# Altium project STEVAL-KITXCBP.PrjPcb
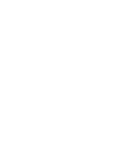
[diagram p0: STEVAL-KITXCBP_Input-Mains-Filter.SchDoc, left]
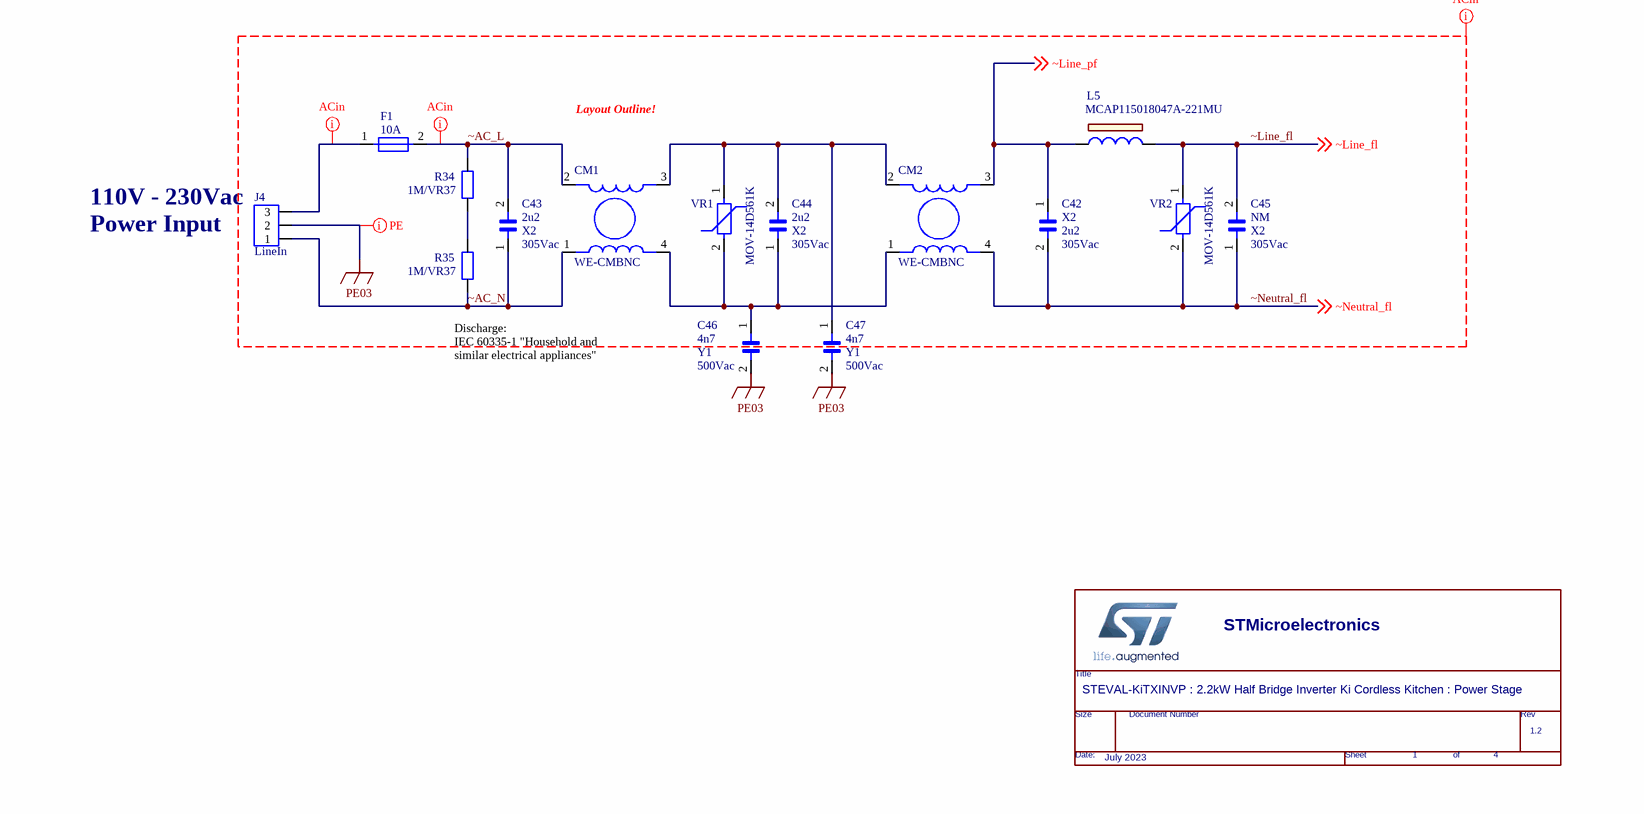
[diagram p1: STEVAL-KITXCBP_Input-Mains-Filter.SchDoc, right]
3 sheets, 268 parts. Net scope: global (net labels, ports and power ports of the same name join across sheets).
Board file: STEVAL-KITXCBP.PcbDoc
Sheets:
  STEVAL-KITXCBP_Input-Mains-Filter.SchDoc
  STEVAL-KITXCBP_Power-Stage.SchDoc
  STEVAL-KITXCBP_Voltage-Regulator.SchDoc

## Sheet STEVAL-KITXCBP_Input-Mains-Filter.SchDoc
size A4; SheetNumber: 1; SheetTotal: 4; PageSetup: Record=PageOptions¦CenterHorizontal=True¦CenterVertical=True¦PrintScale=0.73¦XCorrection=1.00¦YCorrection=1.00¦PrintKind=0¦BorderSize=5000000¦LeftOffset=0¦BottomOffset=0¦Orientation=2¦PaperLength=1000¦PaperWidth=1000¦Scale=100¦PaperSource=15¦PrintQuality=-3¦MediaType=1¦DitherType=10¦PrintScaleMode=1¦PaperKind=A3¦PaperIndex=8

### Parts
(Parts that share a designator on the sheet are numbered #1, #2 ... from top to bottom, then left to right.)
*?#1  Page Create Date: July 2023  RevCode: 1.2  Title: STEVAL-KiTXINVP : 2.2kW Half Bridge Inverter Ki Cordless Kitchen : Power Stage  Page Number: 1  Page Count: 4  (hidden comment: ST_Standard_TitleBlock)  (graphical)
C42  2u2  Dielectric: X2  Voltage: 305Vac  [BLK 13.5 X 32 X P27.5]
C43  2u2  Dielectric: X2  Voltage: 305Vac  [BLK 13.5 X 32 X P27.5]
C44  2u2  Dielectric: X2  Voltage: 305Vac  [BLK 13.5 X 32 X P27.5]
C45  NM  Dielectric: X2  Voltage: 305Vac  [BLK 13.5 X 32 X P27.5]
C46  4n7  Dielectric: Y1  Voltage: 500Vac  [BLK 6X12.5XP10 H12]
C47  4n7  Dielectric: Y1  Voltage: 500Vac  [BLK 6X12.5XP10 H12]
CM1  WE-CMBNC  [WE-CMBNC-MULTI-FOOTPRINT]
CM2  WE-CMBNC  [WE-CMBNC-MULTI-FOOTPRINT]
F1  10A  [FUSEHOLDER]
J4  LineIn  [PX0580/PC]
L5  MCAP115018047A-221MU  [MCAP115018047A]
R34  1M/VR37  [AXIAL0.5]
R35  1M/VR37  [AXIAL0.5]
VR1  MOV-14D561K  [Varistor 14mm]
VR2  MOV-14D561K  [Varistor 14mm]

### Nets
PE03: C46.2 C47.2 J4.2
~AC_L: C43.2 CM1.2 F1.2 R34.2
~AC_N: C43.1 CM1.1 J4.1 R35.1
~Line_fl: C45.2 L5.2 VR2.1 ; off-sheet ~Line_fl  [project net ~Line]
~Line_pf: C42.1 CM2.3 L5.1 ; off-sheet ~Line_pf
~Neutral_fl: C42.2 C45.1 CM2.4 VR2.2 ; off-sheet ~Neutral_fl  [project net ~Neutral]
NetC44_1: C44.1 C46.1 CM1.4 CM2.1 VR1.2
NetC44_2: C44.2 C47.1 CM1.3 CM2.2 VR1.1
NetF1_1: F1.1 J4.3
NetR34_1: R34.1 R35.2

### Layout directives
net class ACin: NetF1_1, PE03, ~AC_L, ~AC_N, ~Line_fl, ~Line_pf, ~Neutral_fl
net class PE: PE03

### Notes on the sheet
- Layout Outline!
- (near J4) 110V - 230Vac
- Power Input
- (near R35) Discharge:
  IEC 60335-1 "Household and similar electrical appliances"

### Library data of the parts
C42-C44 = CAP NP: Capacitor  Non-Polarised; Manufacturer 1: EPCOS; MPN 1: B32924C3225M000; SMT/THT: THT
C45 = CAP NP: Capacitor  Non-Polarised; Manufacturer 1: EPCOS; MPN 1: B32924C3225M000; SMT/THT: THT; Value: 2u2
C46 C47 = CAP NP: Capacitor  Non-Polarised; Manufacturer 1: VISHAY; MPN 1: VY1472M51Y5VQ63V0; SMT/THT: THT; Value: 4n7/Y1
CM1 CM2 = WE-CMBNC: Common Mode Power Line Choke; Manufacturer 1: WURTH ELEKTRONIK; MPN 1: 7448051012; Value: 12mH/10A
F1 = F: FuseHolder 5x20mm
J4 = HEADER3: Power Entry Connector, Plug, 250 VAC, 10 A; Manufacturer 1: Bulgin; MPN 1: PX0580PC; SMT/THT: THT; Value: PX0580PC
L5 = INDUCTOR FERRITE: Inductor 200mH; SMT/THT: THT
R34 = RESISTOR: Resitor Axial; Manufacturer 1: VISHAY; Rated Power: 500mW; SMT/THT: THT; Voltage: 3500V
R35 = RESISTOR: Resitor Axial; Manufacturer 1: VISHAY; MPN 1: VR37000001004JA100; Rated Power: 500mW; SMT/THT: THT; Voltage: 3500V
VR1 VR2 = RVA: Varistor 14mm disc, 350 Vrms, Vdc=560V@1mA,  Pitch=7.5mm; Rated Power: 125J; SMT/THT: THT; Voltage: 350V

## Sheet STEVAL-KITXCBP_Power-Stage.SchDoc
size A2; SheetNumber: 2; SheetTotal: 4; PageSetup: Record=PageOptions¦CenterHorizontal=True¦CenterVertical=True¦PrintScale=0.73¦XCorrection=1.00¦YCorrection=1.00¦PrintKind=0¦BorderSize=5000000¦LeftOffset=0¦BottomOffset=0¦Orientation=2¦PaperLength=1000¦PaperWidth=1000¦Scale=100¦PaperSource=15¦PrintQuality=-3¦MediaType=1¦DitherType=10¦PrintScaleMode=1¦PaperKind=A3¦PaperIndex=8
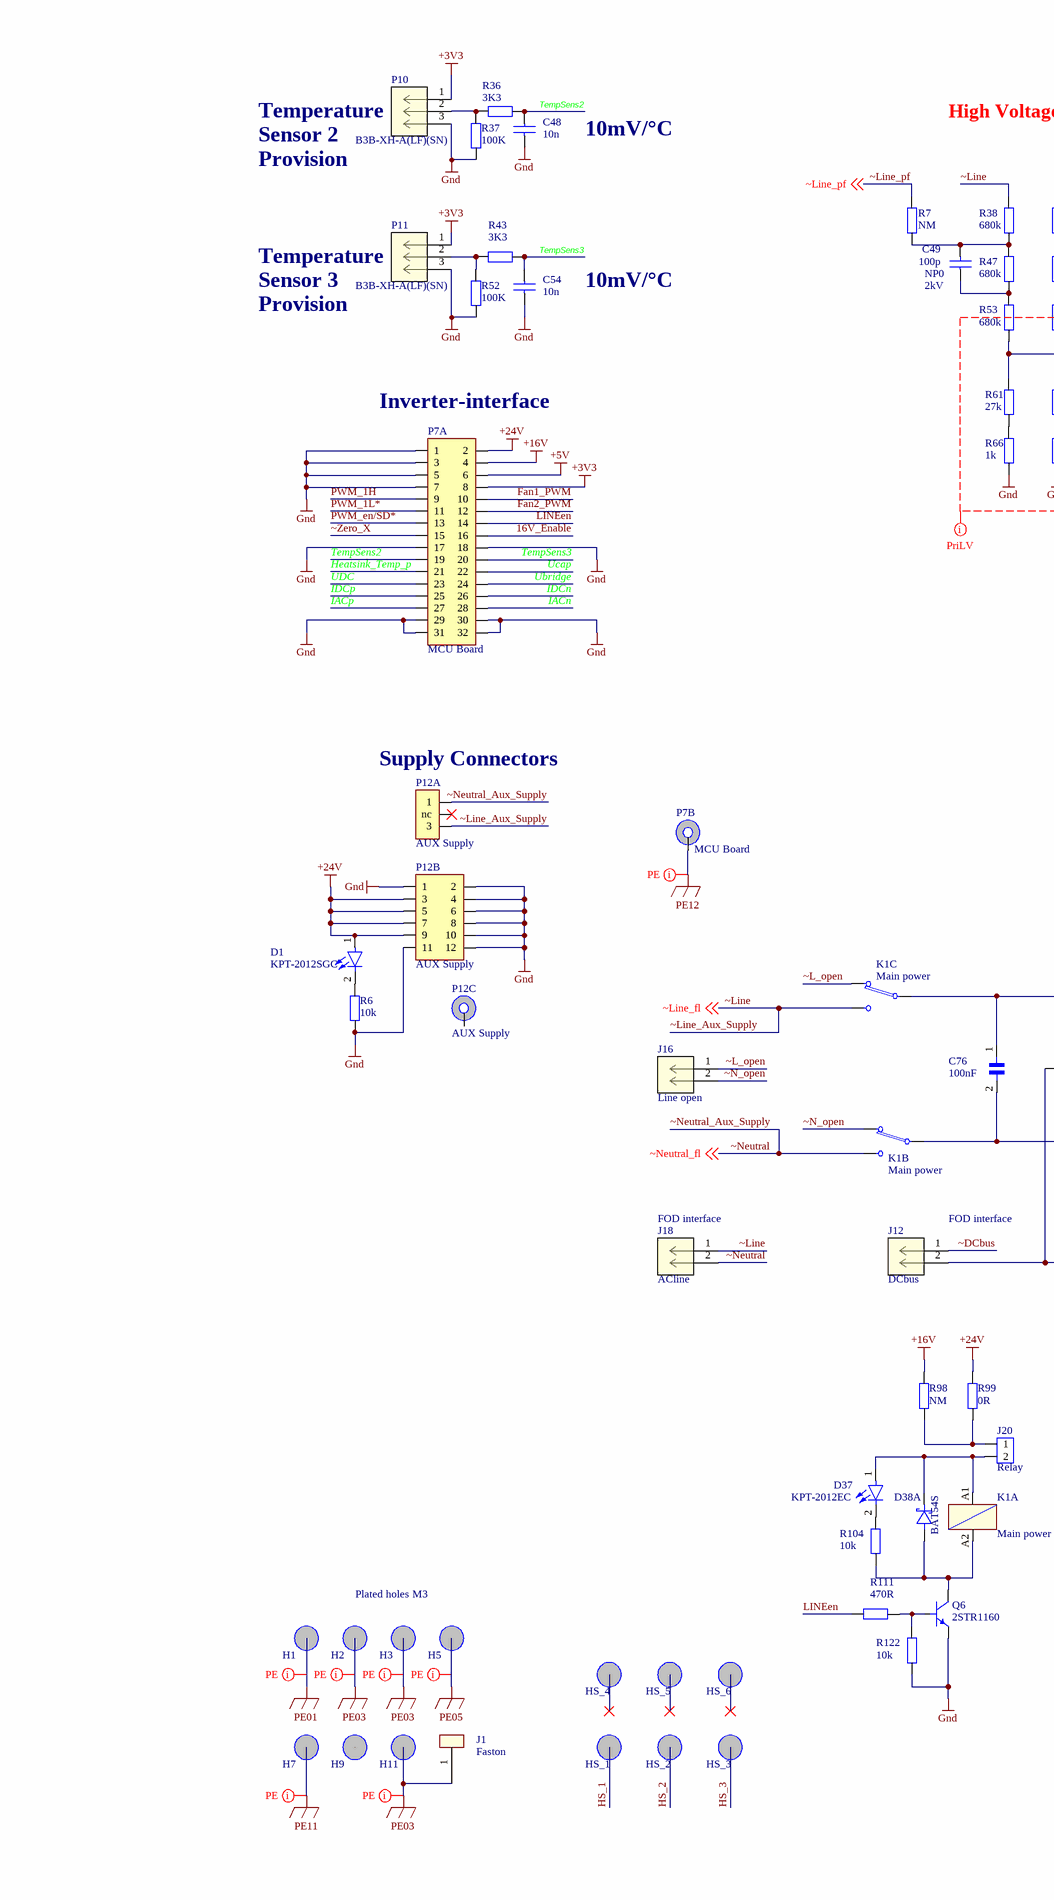
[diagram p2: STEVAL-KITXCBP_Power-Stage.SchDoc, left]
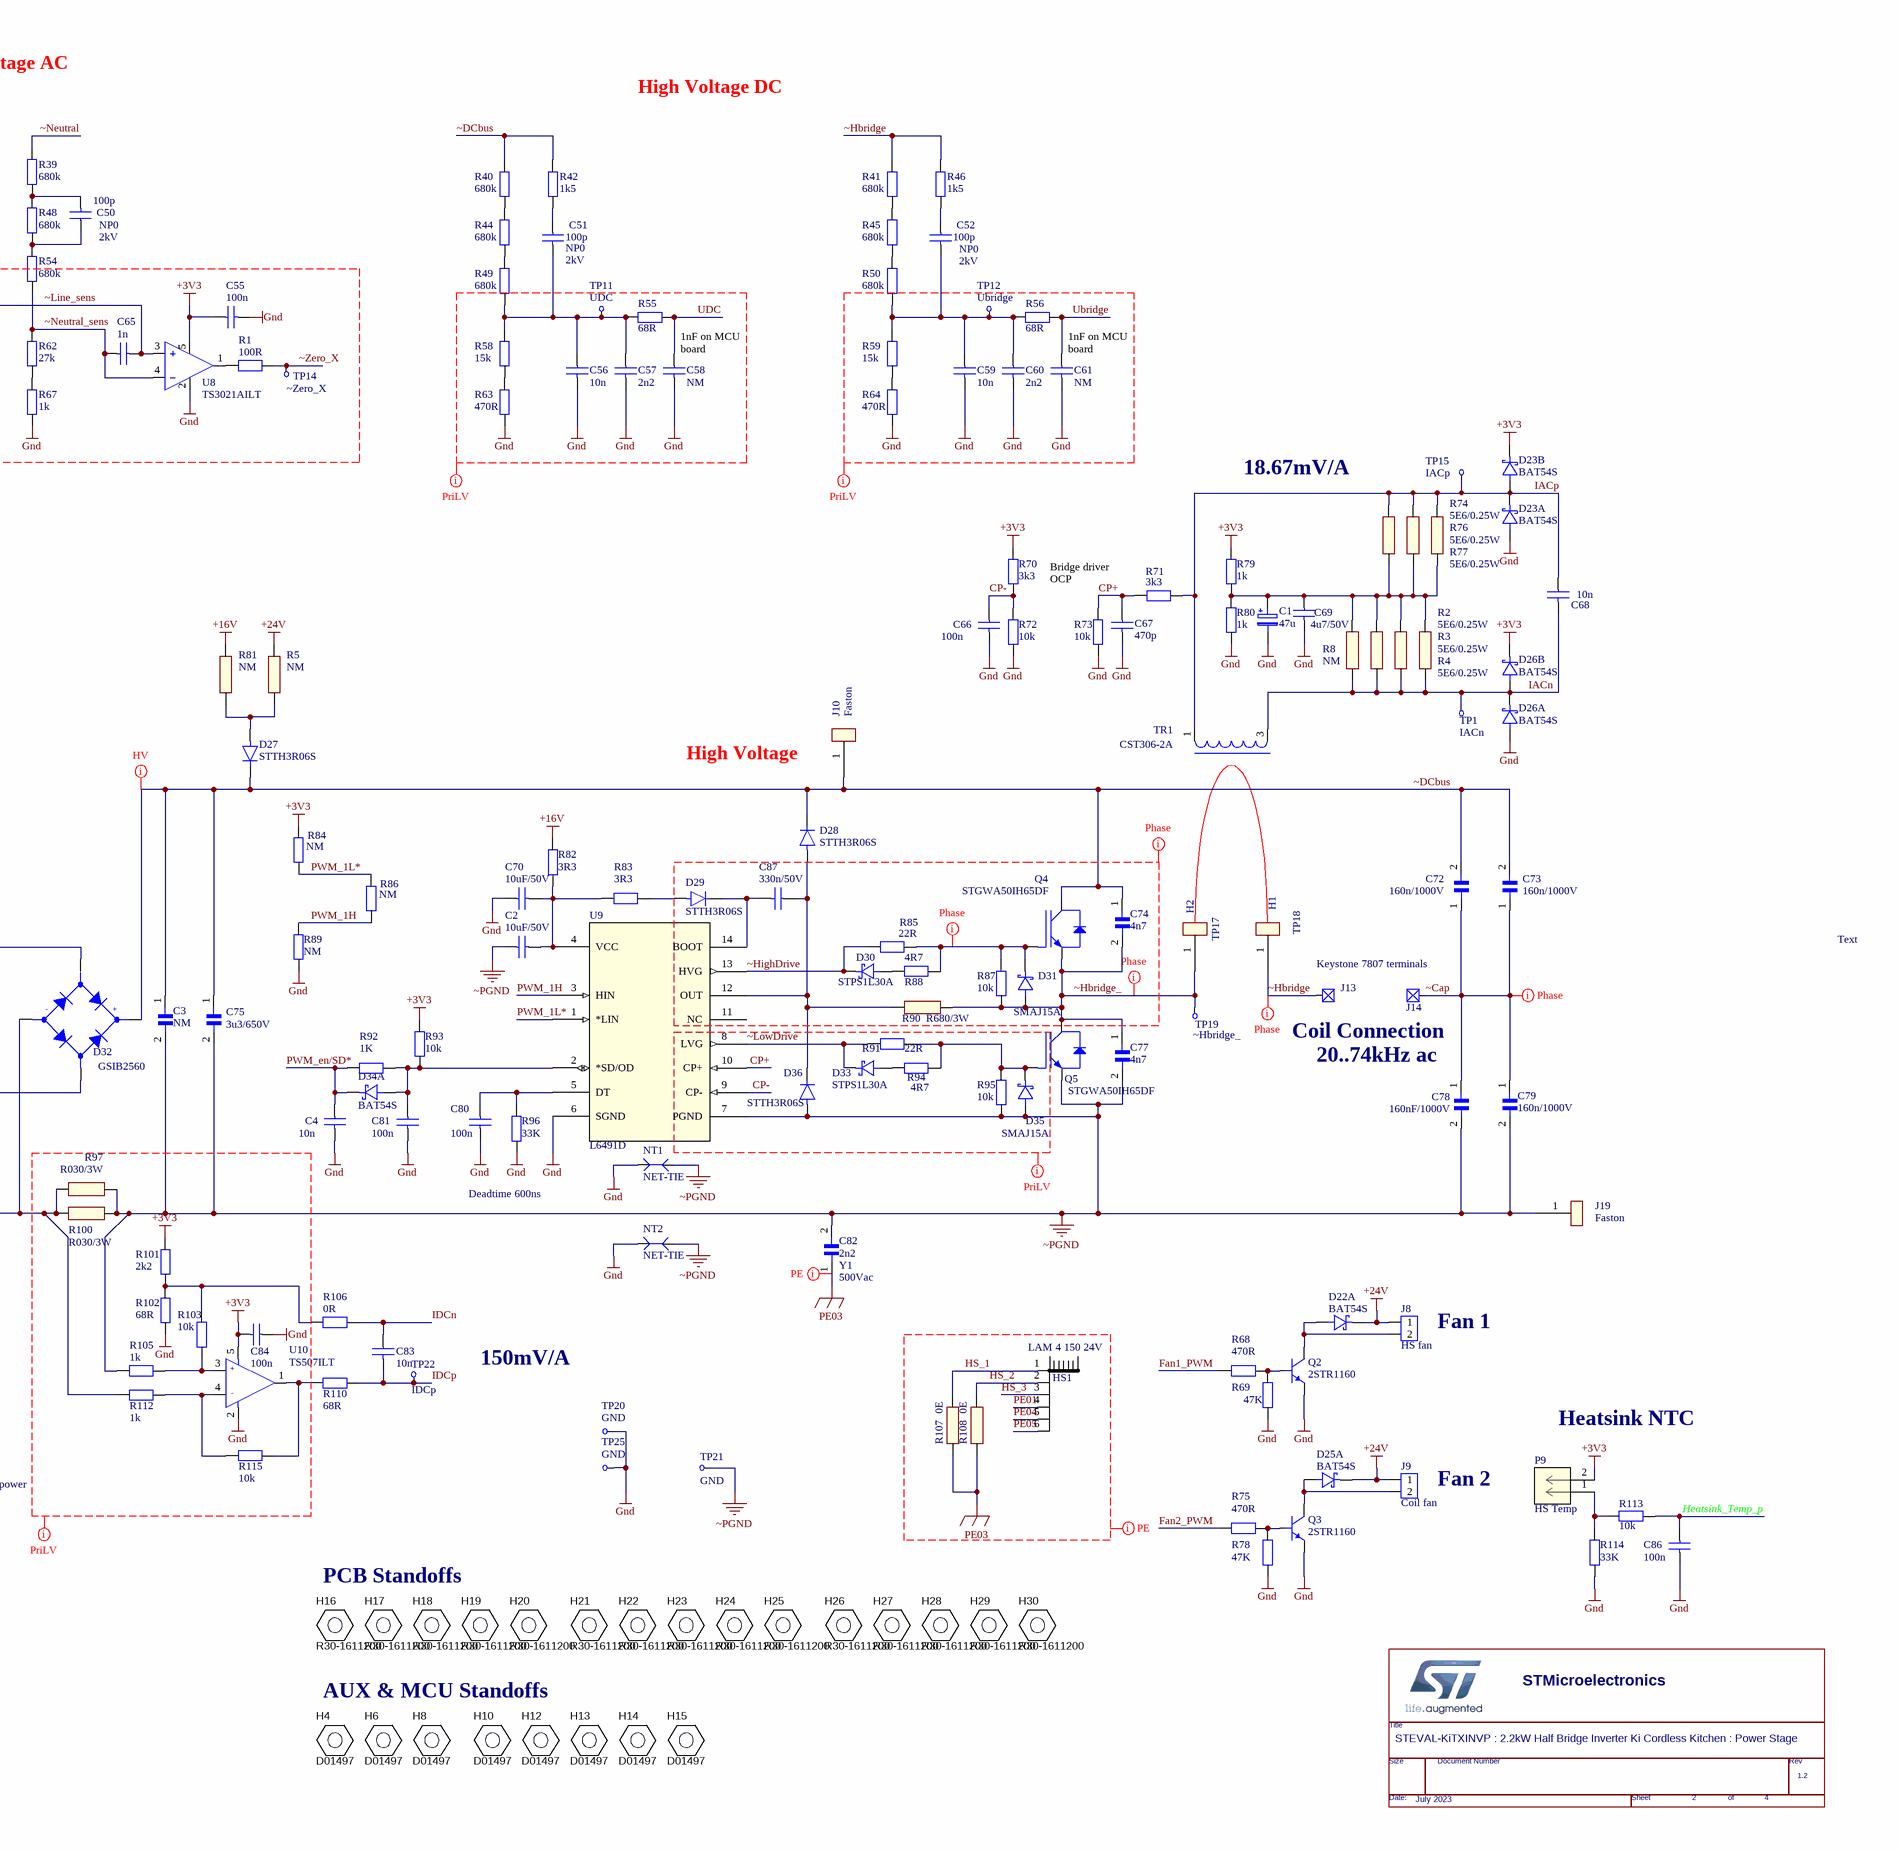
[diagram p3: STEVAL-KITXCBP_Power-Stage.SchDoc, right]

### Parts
(Parts that share a designator on the sheet are numbered #1, #2 ... from top to bottom, then left to right.)
*?#2  Page Create Date: July 2023  RevCode: 1.2  Title: STEVAL-KiTXINVP : 2.2kW Half Bridge Inverter Ki Cordless Kitchen : Power Stage  Page Number: 2  Page Count: 4  (hidden comment: ST_Standard_TitleBlock)  (graphical)
C1  47u  [ELCAP SMD D5H5.8P1.5]
C2  10uF/50V  [CC1210]
C3  NM  [CAPRR1500W80L1800T800H1500A]
C4  10n  [CC0805]
C48  10n  [SMD 0805 CAP]
C49  100p  Dielectric: NP0  Voltage: 2kV  [SMD 1206 CAP]
C50  100p  Dielectric: NP0  Voltage: 2kV  [SMD 1206 CAP]
C51  100p  Dielectric: NP0  Voltage: 2kV  [SMD 1206 CAP]
C52  100p  Dielectric: NP0  Voltage: 2kV  [SMD 1206 CAP]
C54  10n  [SMD 0805 CAP]
C55  100n  [SMD 0805 CAP]
C56  10n  [SMD 0805 CAP]
C57  2n2  [SMD 0805 CAP]
C58  NM  [SMD 0805 CAP]
C59  10n  [SMD 0805 CAP]
C60  2n2  [SMD 0805 CAP]
C61  NM  [SMD 0805 CAP]
C65  1n  [SMD 0805 CAP]
C66  100n  [SMD 0805 CAP]
C67  470p  [SMD 0805 CAP]
C68  10n  [SMD 0805 CAP]
C69  4u7/50V  [CAP SMD 1210small H2.4]
C70  10uF/50V  [CAP SMD 1210small H2.4]
C72  160n/1000V  [Capacitor  Non-Polarised]
C73  160n/1000V  [Capacitor  Non-Polarised]
C74  4n7  [CAPRR1500W80L1800T800H1500A]
C75  3u3/650V  [BLK 22 X 32 X P27.5 H37]
C76  100nF  [BLK 5X18XP15]
C77  4n7  [CAPRR1500W80L1800T800H1500A]
C78  160nF/1000V  [Capacitor  Non-Polarised]
C79  160n/1000V  [Capacitor  Non-Polarised]
C80  100n  [SMD 0805 CAP]
C81  100n  [SMD 0805 CAP]
C82  2n2  Dielectric: Y1  Voltage: 500Vac  [CAPRB1000W60L950T550H1350]
C83  10n  [SMD 0805 CAP]
C84  100n  [SMD 0805 CAP]
C86  100n  [SMD 0805 CAP]
C87  330n/50V  [CAP SMD 1210small H2.4]
D1  KPT-2012SGC  [LED_KPT-2012EC]
D22  BAT54S  [SOT23_3]  (part A of 2)
D23  BAT54S  [SOT23_3]  (parts A,B of 2)
D25  BAT54S  [SOT23_3]  (part A of 2)
D26  BAT54S  [SOT23_3]  (parts A,B of 2)
D27  STTH3R06S  [DO214AB-SMC]
D28  STTH3R06S  [DO214AB-SMC]
D29  STTH3R06S  [DO214AB-SMC]
D30  STPS1L30A  [DO214AC-SMA]
D31  SMAJ15A  [DO214AC-SMA]
D32  GSIB2560  [SIP_GSIB2560-E3/45]
D33  STPS1L30A  [DO214AC-SMA]
D34  BAT54S  [SOT23_3]  (part A of 2)
D35  SMAJ15A  [DO214AC-SMA]
D36  STTH3R06S  [DO214AB-SMC]
D37  KPT-2012EC  [LED_KPT-2012EC]
D38  BAT54S  [SOT23_3]  (part A of 2)
H1  Hole  [p-hole-m3]  (value not drawn)  (no BOM)
H2  Hole  [p-hole-m3]  (value not drawn)  (no BOM)
H3  Hole  [p-hole-m3]  (value not drawn)  (no BOM)
H4  D01497  [Keystone_1902C]
H5  Hole  [p-hole-m3]  (value not drawn)  (no BOM)
H6  D01497  [Keystone_1902C]
H7  Hole  [p-hole-m3]  (value not drawn)  (no BOM)
H8  D01497  [Keystone_1902C]
H9  Hole  [p-hole-m3]  (value not drawn)  (no BOM)
H10  D01497  [Keystone_1902C]
H11  Hole  [p-hole-m3]  (value not drawn)  (no BOM)
H12  D01497  [Keystone_1902C]
H13  D01497  [Keystone_1902C]
H14  D01497  [Keystone_1902C]
H15  D01497  [Keystone_1902C]
H16  R30-1611200  [Keystone_1902C]
H17  R30-1611200  [Keystone_1902C]
H18  R30-1611200  [Keystone_1902C]
H19  R30-1611200  [Keystone_1902C]
H20  R30-1611200  [Keystone_1902C]
H21  R30-1611200  [Keystone_1902C]
H22  R30-1611200  [Keystone_1902C]
H23  R30-1611200  [Keystone_1902C]
H24  R30-1611200  [Keystone_1902C]
H25  R30-1611200  [Keystone_1902C]
H26  R30-1611200  [Keystone_1902C]
H27  R30-1611200  [Keystone_1902C]
H28  R30-1611200  [Keystone_1902C]
H29  R30-1611200  [Keystone_1902C]
H30  R30-1611200  [Keystone_1902C]
HS1  LAM 4 150 24V  [Heatsink + Fan 150 x 40 x 40mm + Holes]
HS_1  Hole  [p-hole-m3]  (value not drawn)  (no BOM)
HS_2  Hole  [p-hole-m3]  (value not drawn)  (no BOM)
HS_3  Hole  [p-hole-m3]  (value not drawn)  (no BOM)
HS_4  Hole  [p-hole-m3]  (value not drawn)  (no BOM)
HS_5  Hole  [p-hole-m3]  (value not drawn)  (no BOM)
HS_6  Hole  [p-hole-m3]  (value not drawn)  (no BOM)
J1  Faston  [TAB]
J8  HS fan  [CONNECTOR P2.5 MALE]
J9  Coil fan  [CONNECTOR P2.5 MALE]
J10  Faston  [TAB]
J12  DCbus  [Connector P5.08]
J13  7807  [Keystone 7807]  (value not drawn)
J14  7807  [Keystone 7807]  (value not drawn)
J16  Line open  [Connector P5.08]
J18  ACline  [Connector P5.08]
J19  Faston  [TAB]
J20  Relay  [CONNECTOR P2.5 MALE]
K1  Main power  [Finder 44.62]  (parts A,B,C of 3)
NT1  NET-TIE  [Net-Tie-0.3mm]  (net tie, no BOM)
NT2  NET-TIE  [Net-Tie_0805_HV_NoOverlay]  (net tie, no BOM)
P7  MCU Board  [ST MCU BOARD]  (parts A,B of 2)
P9  HS Temp  [CONNECTOR P2.5 MALE]
P10  B3B-XH-A(LF)(SN)  [CONNECTOR P2.5 MALE 3WAY]
P11  B3B-XH-A(LF)(SN)  [CONNECTOR P2.5 MALE 3WAY]
P12  AUX Supply  [ST AUX SUPPLY]  (parts A,B,C of 3)
Q2  2STR1160  [SOT23_3]
Q3  2STR1160  [SOT23_3]
Q4  STGWA50IH65DF  [TO247]
Q5  STGWA50IH65DF  [TO247]
Q6  2STR1160  [SOT23_3]
R1  100R  [SMD 0805]
R2  5E6/0.25W  [VSMP_1206]  (no BOM)
R3  5E6/0.25W  [VSMP_1206]
R4  5E6/0.25W  [VSMP_1206]
R5  NM  [VSMP_2512]  (no BOM)
R6  10k  [RC0805]
R7  NM  [RC1206]
R8  NM  [VSMP_1206]
R36  3K3  [SMD 0805]
R37  100K  [SMD 0805]
R38  680k  [SMD 1206]
R39  680k  [SMD 1206]
R40  680k  [SMD 1206]
R41  680k  [SMD 1206]
R42  1k5  [SMD 1206]
R43  3K3  [SMD 0805]
R44  680k  [SMD 1206]
R45  680k  [SMD 1206]
R46  1k5  [SMD 1206]
R47  680k  [SMD 1206]
R48  680k  [SMD 1206]
R49  680k  [SMD 1206]
R50  680k  [SMD 1206]
R52  100K  [SMD 0805]
R53  680k  [SMD 1206]
R54  680k  [SMD 1206]
R55  68R  [SMD 0805]
R56  68R  [SMD 0805]
R58  15k  [SMD 0805]
R59  15k  [SMD 0805]
R61  27k  [SMD 0805]
R62  27k  [SMD 0805]
R63  470R  [SMD 0805]
R64  470R  [SMD 0805]
R66  1k  [SMD 0805]
R67  1k  [SMD 0805]
R68  470R  [SMD 0805]
R69  47K  [SMD 0805]
R70  3k3  [SMD 0805]
R71  3k3  [SMD 0805]
R72  10k  [SMD 0805]
R73  10k  [SMD 0805]
R74  5E6/0.25W  [VSMP_1206]  (no BOM)
R75  470R  [SMD 0805]
R76  5E6/0.25W  [VSMP_1206]
R77  5E6/0.25W  [VSMP_1206]
R78  47K  [SMD 0805]
R79  1k  [SMD 0805]
R80  1k  [SMD 0805]
R81  NM  [VSMP_2512]  (no BOM)
R82  3R3  [RES SMD 1206]
R83  3R3  [RES SMD 1206]
R84  NM  [SMD 0805]
R85  22R  [SMD 0805]
R86  NM  [SMD 0805]
R87  10k  [SMD 0805]
R88  4R7  [SMD 0805]
R89  NM  [SMD 0805]
R90  R680/3W  [2512welwyn]
R91  22R  [SMD 0805]
R92  1K  [SMD 0805]
R93  10k  [SMD 0805]
R94  4R7  [SMD 0805]
R95  10k  [SMD 0805]
R96  33K  [SMD 0805]
R97  R030/3W  [2512welwyn]
R98  NM  [SMD 0805]  (no BOM)
R99  0R  [SMD 0805]
R100  R030/3W  [2512welwyn]
R101  2k2  [SMD 0805]
R102  68R  [SMD 0805]
R103  10k  [SMD 0805]
R104  10k  [SMD 0805]
R105  1k  [SMD 0805]
R106  0R  [SMD 0805]
R107  0E  [2512welwyn]  (no BOM)
R108  0E  [2512welwyn]  (no BOM)
R110  68R  [SMD 0805]
R111  470R  [SMD 0805]
R112  1k  [SMD 0805]
R113  10k  [SMD 0805]
R114  33K  [SMD 0805]
R115  10k  [SMD 0805]
R122  10k  [SMD 0805]
TP1  IACn  [TP_20-313142]
TP11  UDC  [Terminal]
TP12  Ubridge  [Terminal]
TP14  ~Zero_X  [Terminal]
TP15  IACp  [Terminal]
TP17  H2  [TEST POINT]  (no BOM)
TP18  H1  [TEST POINT]  (no BOM)
TP19  ~Hbridge_  [Terminal]
TP20  GND  [Terminal]
TP21  GND  [Terminal]
TP22  IDCp  [Terminal]
TP25  GND  [Terminal]
TR1  CST306-2A  [Coil5600]
U8  TS3021AILT  [SOT23_5]
U9  L6491D  [SOIC_491D_STM]
U10  TS507ILT  [SOT23_5leadC]

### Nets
+3V3: C55.1 C84.2 D23.2(Cathode) D26.2(Cathode) P7.8 P9.2 P10.1 P11.1 R70.2 R79.2 R84.2 R93.2 R101.2 U8.5(VDD) U10.5
+5V: P7.6
+16V: P7.4 R81.1(R1) R82.2 R98.2
+24V: D1.1 D22.3(Cathode) D25.3(Cathode) J8.1 J9.1 P7.2 P12.5(3) P12.7(5) P12.9(7) P12.11(9) R5.1(R1) R99.2
Gnd: C1.2(-) C4.2 C48.2 C54.2 C55.2 C56.2 C57.2 C58.2 C59.2 C60.2 C61.2 C66.2 C67.2 C69.2 C70.1 C80.2 C81.2 C84.1 C86.2 D23.1(Anode) D26.1(Anode) NT1.2 NT2.2 P7.1 P7.3 P7.5 P7.7 P7.17 P7.18 P7.29 P7.30 P7.31 P7.32 P10.3 P11.3 P12.3(1) P12.4(2) P12.6(4) P12.8(6) P12.10(8) P12.12(10) P12.13(11) P12.14(12) Q2.2(E) Q3.2(E) Q6.2(E) R6.1 R37.1 R52.1 R63.2 R64.2 R66.1 R67.2 R69.1 R72.1 R73.1 R78.1 R80.2 R89.1 R96.2 R102.1 R114.2 R122.1 TP20.1(AmpIn) TP25.1(AmpIn) U8.2(VSS) U9.6(SGND) U10.2
PE01: H1.1 HS1.4
PE03: C82.1 H2.1 H3.1 H11.1 J1.1 R107.1(R1) R108.1(R1)
PE05: H5.1 HS1.6
PE11: H7.1
PE12: P7.MH
~PGND: C2.1 C3.2 C75.2 C77.2 C78.2 C79.2 C82.2 D35.1(Anode) D36.1 J19.1 NT1.1 NT2.1 Q5.3(E) R95.2 R97.1(R1) R100.1(R1) R105.1 TP21.1(AmpIn) U9.7(PGND)
16V_Enable: P7.16
CP+: C67.1 R71.1 R73.2 U9.10(CP+)
CP-: C66.1 R70.1 R72.2 U9.9(CP-)
Fan1_PWM: P7.10 R68.1
Fan2_PWM: P7.12 R75.1
Heatsink_Temp_p: C86.1 P7.21 R113.2
HS_1: HS1.1 HS_1.1 R107.2(R2)
HS_2: HS1.2 HS_2.1 R108.2(R2)
HS_3: HS1.3 HS_3.1
IACn: C68.2 D26.3(Cathode) P7.28 R2.1(R1) R3.2(R2) R4.1(R1) R8.2(R2) TP1.1(AmpIn) TR1.3
IACp: C68.1 D23.3(Cathode) P7.27 R71.2 R74.2(R2) R76.1(R1) R77.2(R2) TP15.1(AmpIn) TR1.1
IDCn: C83.1 P7.26 R106.1
IDCp: C83.2 P7.25 R110.1 TP22.1(AmpIn)
LINEen: P7.14 R111.1
PE04: HS1.5
PWM_1H: P7.9 R86.1 R89.2 U9.3(HIN)
PWM_1L*: P7.11 R84.1 R86.2 U9.1(*LIN)
PWM_en/SD*: C4.1 D34.3(Cathode) P7.13 R92.1
TempSens2: C48.1 P7.19 R36.1
TempSens3: C54.1 P7.20 R43.1
Ubridge: C61.1 P7.24 R56.1
Ucap: P7.22
UDC: C58.1 P7.23 R55.1
~Cap: C72.1 C73.1 C78.1 C79.1 J14.1
~DCbus: C3.1 C72.2 C73.2 C74.1 C75.1 D27.2 D28.2 D32.1(+DC) J10.1 J12.1 Q4.2(C) R40.2 R42.2
~Hbridge: J13.1 R41.2 R46.2 TP18.1
~Hbridge_: C74.2 C77.1 D31.1(Anode) Q4.3(E) Q5.2(C) R87.2 R90.1(R1) TP17.1 TP19.1(AmpIn)
~HighDrive: D30.2(Cathode) R85.1 U9.13(HVG)
~L_open: J16.1 K1.22(NC)
~Line: J18.1 K1.24(NO) P12.2(3) R38.2 ; off-sheet ~Line_fl  [also labelled ~Line_Aux_Supply, ~Line_fl]
~Line_pf: R7.1 ; off-sheet ~Line_pf
~Line_sens: C65.1 R53.1 R61.2 U8.3(IN+)
~LowDrive: D33.2(Cathode) R91.1 U9.8(LVG)
~N_open: J16.2 K1.12(NC)
~Neutral: J18.2 K1.14(NO) P12.1 R39.1 ; off-sheet ~Neutral_fl  [also labelled ~Neutral_Aux_Supply, ~Neutral_fl]
~Neutral_sens: C65.2 R54.2 R62.2 U8.4(IN-)
~Zero_X: P7.15 R1.2 TP14.1(AmpIn)
NetC1_1: C1.1(+) C69.1 R2.2(R2) R3.1(R1) R4.2(R2) R8.1(R1) R74.1(R1) R76.2(R2) R77.1(R1) R79.1 R80.1
NetC2_2: C2.2 C70.2 R82.1 R83.1 U9.4(VCC)
NetC49_1: C49.1 R47.1 R53.2
NetC49_2: C49.2 R7.2 R38.1 R47.2
NetC50_1: C50.1 R48.2 R54.1
NetC50_2: C50.2 R39.2 R48.1
NetC51_1: C51.1 R42.1
NetC51_2: C51.2 C56.1 C57.1 R49.1 R55.2 R58.2 TP11.1(AmpIn)
NetC52_1: C52.1 R46.1
NetC52_2: C52.2 C59.1 C60.1 R50.1 R56.2 R59.2 TP12.1(AmpIn)
NetC76_1: C76.1 D32.2(AC1) K1.21(C)
NetC76_2: C76.2 D32.3(AC2) K1.11(C)
NetC80_1: C80.1 R96.1 U9.5(DT)
NetC81_1: C81.1 D34.1(Anode) R92.2 R93.1 U9.2(*SD/OD)
NetC87_1: C87.1 D28.1 D36.2 R90.2(R2) U9.12(OUT)
NetC87_2: C87.2 D29.2 U9.14(BOOT)
NetD1_2: D1.2 R6.2
NetD22_1: D22.1(Anode) J8.2 Q2.3(C)
NetD25_1: D25.1(Anode) J9.2 Q3.3(C)
NetD27_1: D27.1 R5.2(R2) R81.2(R2)
NetD29_1: D29.1 R83.2
NetD30_1: D30.1(Anode) R88.2
NetD31_2: D31.2(Cathode) Q4.1(G) R85.2 R87.1 R88.1
NetD32_4: D32.4(-DC) J12.2 R97.2(R2) R100.2(R2) R112.1
NetD33_1: D33.1(Anode) R94.2
NetD35_2: D35.2(Cathode) Q5.1(G) R91.2 R94.1 R95.1
NetD37_1: D37.1 D38.3(Cathode) J20.2 K1.A1
NetD37_2: D37.2 R104.2
NetD38_1: D38.1(Anode) K1.A2 Q6.3(C) R104.1
NetJ20_1: J20.1 R98.1 R99.1
NetP9_1: P9.1 R113.1 R114.1
NetP10_2: P10.2 R36.2 R37.2
NetP11_2: P11.2 R43.2 R52.2
NetQ2_1: Q2.1(B) R68.2 R69.2
NetQ3_1: Q3.1(B) R75.2 R78.2
NetQ6_1: Q6.1(B) R111.2 R122.2
NetR1_1: R1.1 U8.1(OUT)
NetR40_1: R40.1 R44.2
NetR41_1: R41.1 R45.2
NetR44_1: R44.1 R49.2
NetR45_1: R45.1 R50.2
NetR58_1: R58.1 R63.1
NetR59_1: R59.1 R64.1
NetR61_1: R61.1 R66.2
NetR62_1: R62.1 R67.1
NetR101_1: R101.1 R102.2 R103.2 R106.2
NetR103_1: R103.1 R105.2 U10.3
NetR110_2: R110.2 R115.2 U10.1
NetR112_2: R112.2 R115.1 U10.4

Not connected (* = marked no-connect by the designer): H9 1; HS_4 1*; HS_5 1*; HS_6 1*; P12 ?1(nc)* MH; U9 11(NC)

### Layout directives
net class PriLV: +3V3, CP+, CP-, Gnd, Ubridge, UDC, ~Line_sens, ~LowDrive, ~Neutral_sens, ~Zero_X
net class PE: HS_1, HS_2, HS_3, PE01, PE03, PE04, PE05, PE11, PE12
net class Phase: NetD31_2, ~Cap, ~Hbridge, ~Hbridge_, ~HighDrive
net class HV: ~DCbus

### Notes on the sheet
- Temperature
- Sensor 2
- 10mV/°C
- High Voltage AC
- High Voltage DC
- Provision
- Sensor 3
- 1nF on MCU board
- (near P7) Inverter-interface
- 18.67mV/A
- Bridge driver OCP
- (near P12) Supply Connectors
- High Voltage
- Text
- Keystone 7807 terminals
- Coil Connection
- (near C78) 20..74kHz ac
- (near J18) FOD interface
- (near J12) FOD interface
- Deadtime 600ns
- 150mV/A
- (near J8) Fan 1
- Heatsink NTC
- (near J9) Fan 2
- Plated holes M3
- PCB Standoffs
- AUX & MCU Standoffs

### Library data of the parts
C1 = Capacitor P_2: Cap Aluminum 47uF 16V 20% (5 X 5.8mm) SMD 0.36 Ohm 240mA 2000 hr 105°C Embossed T/R; Manufacturer 1: Panasonic; Manufacturer Part Number 1: EEE-FPC470UAR; Material: Aluminium; ESR (Equivalent Series Resistance): 360mR; Leakage Current: 7.5uA; Life (Hours): 2000Hour
C2 C70 = CAP NP: Capacitor  1210; Dielectric: X7R; SMT/THT: SMT; Value: 10u/50V; Voltage: 50V
C3 = CAP NP: Capacitor  Non-Polarised; Manufacturer 1: WIMA; MPN 1: FKP1O121004F00KSSD; Dielectric: PP; SMT/THT: THT; Value: 10n; Voltage: 1kV
C4 C48 C54-C56 C58 C59 C61 C65-C68 C80 C81 C83 C84 C86 = CAP NP: Capacitor  0805; Manufacturer 1: VISHAY; MPN 1: VJ0805Y104KXACW1BC; Dielectric: X7R; SMT/THT: SMT; Voltage: 50V
C49-C52 = CAP NP: Capacitor  1206; Manufacturer 1: VISHAY; MPN 1: 885342008011; SMT/THT: SMT
C57 C60 = CAP NP: Capacitor  0805; Manufacturer 1: VISHAY; MPN 1: VJ0805Y222JXAPW1BC; Dielectric: X7R; SMT/THT: SMT; Voltage: 50V
C69 = CAP NP: Capacitor  1210; Manufacturer 1: MURATA; MPN 1: 12105C475KAT2A; Dielectric: X7R; SMT/THT: SMT; Voltage: 50V
C72 C73 C78 C79 = CAP NP: Capacitor  Non-Polarised; Manufacturer 1: KEMET; MPN 1: R73QW3160ZMK0J; SMT/THT: THT; Value: 2u2; Voltage: 400Vac; Dielectric: PP
C74 C77 = CAP NP: Capacitor  Non-Polarised; Manufacturer 1: WIMA; MPN 1: FKP1R014704D00KSSD; Dielectric: PP; SMT/THT: THT; Voltage: 1.25kV
C75 = CAP NP: Capacitor  Non-Polarised; Manufacturer 1: EPCOS; MPN 1: B32674D6335K000; Value: 3u3; Voltage: 650V; SMT/THT: THT
C76 = CAP NP: Capacitor  Non-Polarised; Manufacturer 1: EPCOS; MPN 1: B32922C3104M000; Dielectric: X2; SMT/THT: THT; Voltage: 305Vac
C82 = CAP NP: Capacitor  Non-Polarised; Manufacturer 1: VISHAY; MPN 1: VY1222M37Y5VQ63V0; SMT/THT: THT; Value: 2n2/Y1
C87 = CAP NP: Capacitor  1210; Manufacturer 1: MURATA; MPN 1: 12105C475KAT2A; Dielectric: X7R; SMT/THT: SMT; Value: 4u7/50V; Voltage: 50V
D1 D37 = DIODE LED: LED; Manufacturer 1: KINGBRIGHT; Colour: Red; SMT/THT: SMT
D22 D23 D25 D26 D34 D38 = Diode Dual BAT54S: Dual series Schottky Diode; Manufacturer 1: STMicroelectronics; Manufacturer Part Number 1: BAT54SFILM
D27-D29 D36 = DIODE: Manufacturer 1: ST; MPN 1: STTH1R06A; SMT/THT: SMT; Current: 1A; Voltage: 600V
D30 D31 D33 D35 = Diode STPS1L30A: Small Signal Schottky Diode; Max Surge Current: 75A; Forward Current: 1A; Max Reverse Current: 200uA; Forward Voltage: 395mV; Max Repetitive Reverse Voltage (Vrrm): 30V; Element Configuration: Single; Polarity: Standard
D32 = BRIDGE: Bridge Rectifier; Manufacturer 1: VISHAY; MPN 1: GSIB2560-E3/45; Current: 25A; SMT/THT: THT; Voltage: 600V
H4 H6 H8 H10 H12-H15 = CMP-0003610-1: Standoffs & Spacers NYLON 12mm Height M3; Manufacturer: Duratool; CompType: Hardware; Key: 1902C
H16-H30 = CMP-0003610-1: Standoffs & Spacers NYLON 12mm Height M3; Manufacturer: Harwin; CompType: Hardware; Key: 1902C
HS1 = LAM 4 100 12 V
J1 J10 J19 = TEST POINT
J8 = HEADER2: 2 pin JST connector; MPN 1: B2B-XH-A; PVC/BFR?: Yes; SMT/THT: THT; Value: B2B-XH-A
J9 J20 = HEADER2: 2 pin JST connector; MPN 1: B2B-XH-A; SMT/THT: THT; TSL: Yes; Value: B2B-XH-A
J12 J16 J18 = 1729128: TE Connectivity 1-917337-5
J13 J14 = HEADER1: Screw on Terminal; SMT/THT: NA; System: Connector
K1 = RELAY-DPDT 2CO: Dual-Pole Dual-Throw Relay; MPN 1: 40.62.7.024.4000; Manufacturer 1: Finder; SMT/THT: THT; Value: 40.62.7.024.4000; Current: 10A
P7 = ST inverter MCU Board: TSW-116-07-G-D
P9 = B2B-XH-A(LF)(SN): CONNECTOR HEADER, XH SERIES, 2 POSITION, 2.50MM, Press-Fit Solder, Detent Lock, Natural; Manufacturer 1: JST
P10 P11 = B3B-XH-A(LF)(SN): 3 pin JST connector
P12 = ST inverter AUX supply board: 2 x TSW-103-07-G-S-002 + TSW-106-07-G-D
Q2 Q3 Q6 = NPN 2STR1160: NPN Bipolar Transistor; Manufacturer 1: STMicroelectronics; hFE Min: 180; Max Power Dissipation: 500mW; Number of Elements: 1; Collector Emitter Voltage (VCEO): 60V; Max Collector Current: 1A; Emitter Base Voltage (VEBO): 5V; Collector Emitter Saturation Voltage: 430mV; Element Configuration: Single
Q4 Q5 = IKW30N60H3: 100 A, 1.5 V, 300 W, 650 V; TSL: Yes; SMT/THT: THT; Current: 150A; Voltage: 650V
R1 R6 R36 R37 R43 R52 R55 R56 R58 R59 R61-R64 R66-R73 R75 R78-R80 R82-R89 R91-R96 R98 R99 R101-R106 R110-R115 R122 = RESISTOR: RESISTOR 0805; SMT/THT: SMT
R2-R4 R74 R76 R77 = RES: Resistor 1206; Rated Power: 1W; SMT/THT: SMT; Tolerance: 1%
R5 R81 R107 R108 = RES: Resistor 2512; Rated Power: 1W; SMT/THT: SMT
R7 R38-R41 R44 R45 R47-R50 R53 R54 = RESISTOR: Res Thick Film 1206 681K Ohm 1% 0.25W(1/4W) ±200ppm/C Epoxy Pad SMD T/R; Manufacturer 1: Yageo; Manufacturer Part Number 1: RV1206FR-07681KL; Value: 681kR; Power Rating: 250mW; Voltage Rating: 500V; Temperature Coefficient: 200ppm/°C
R8 = RES: CRCW Series 1206 0.25 W 0 Ohm Jumper Surface Mount Thick Film Chip Resistor
R42 R46 = RESISTOR: Resistor 1206; Manufacturer 1: VISHAY; MPN 1: CRCW120668K0FKEA; SMT/THT: SMT; Tolerance: 1%; Voltage: 200V
R90 = RES: Resistor 2512; Rated Power: 2W; SMT/THT: SMT; Tolerance: 5%; Value: R680
R97 R100 = RES: Resistor 2512; Rated Power: 3W; SMT/THT: SMT; Tolerance: 1%; Value: R030
TP1 TP11 TP12 TP14 TP15 TP19-TP22 TP25 = TESTP: Test Point; SMT/THT: THT
TP17 TP18 = TEST POINT: SMT/THT: NA; Value: NA
TR1 = 56050C_5: Current Transfomer; SMT/THT: THT
U8 = Comparator TS3021AILT: Single OPAMP 5 pin package; Manufacturer 1: STMicroelectronics; Min Supply Voltage: 1.8V; Max Supply Voltage: 5V
U9 = L6491D: Half Bridge Driver; Built_By: EMA_Matt; Vendor: STMicroelectronics; SourceLibrary: Updates_to_database_2020-11-10
U10 = MCP6561: 1.8V Low Power Push-Pull Output Comparator; TSL: Yes; SMT/THT: SMT

## Sheet STEVAL-KITXCBP_Voltage-Regulator.SchDoc
size A3; SheetNumber: 4; SheetTotal: 4
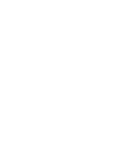
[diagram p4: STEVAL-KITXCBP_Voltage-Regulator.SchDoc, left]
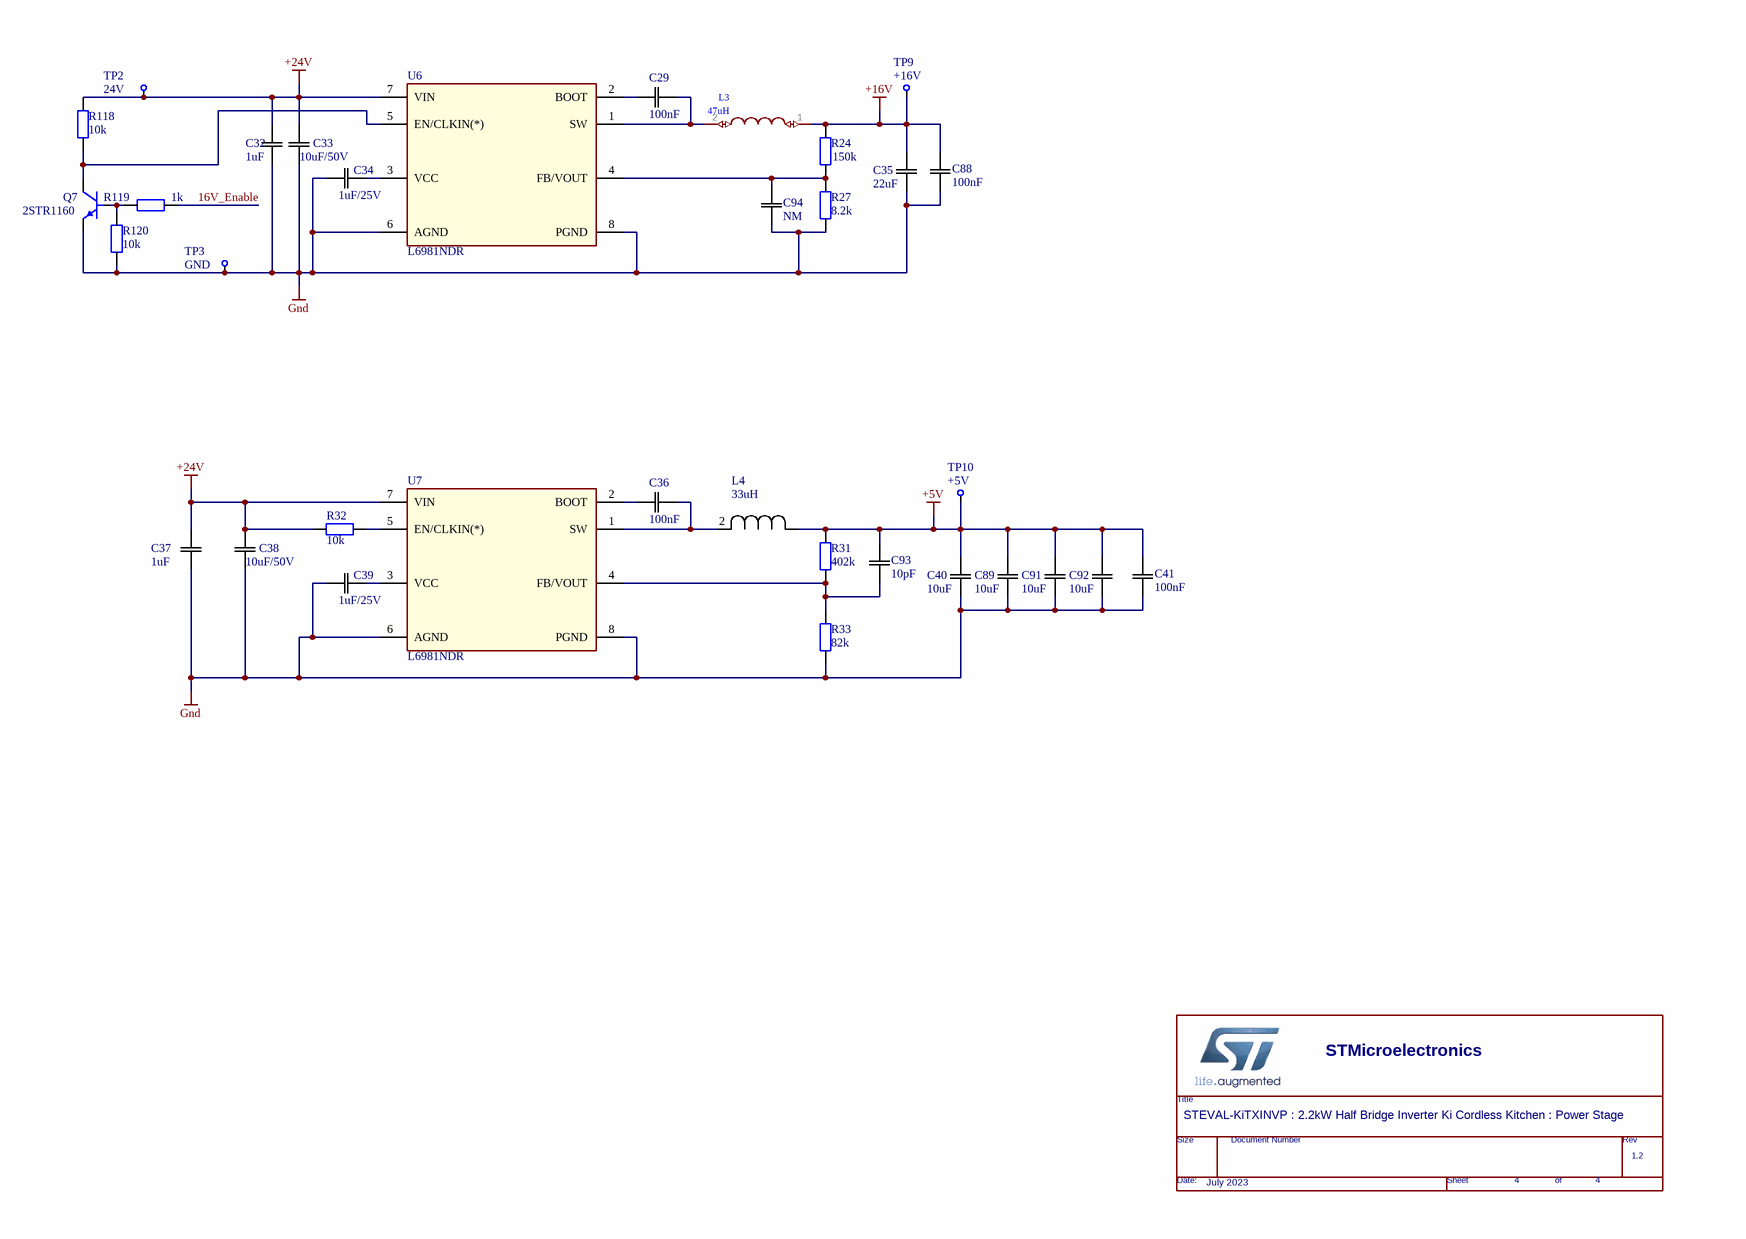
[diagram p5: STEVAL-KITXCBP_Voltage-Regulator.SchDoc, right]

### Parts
(Parts that share a designator on the sheet are numbered #1, #2 ... from top to bottom, then left to right.)
*?#3  Page Create Date: July 2023  RevCode: 1.2  Title: STEVAL-KiTXINVP : 2.2kW Half Bridge Inverter Ki Cordless Kitchen : Power Stage  Page Number: 4  (hidden comment: ST_Standard_TitleBlock)  (graphical)
C29  100nF  [CAP_0805J_AVX]
C32  1uF  [CAP_0805J_AVX]
C33  10uF/50V  [CC1206]
C34  1uF/25V  [CC1206]
C35  22uF  [CC1206]
C36  100nF  [CAP_0805J_AVX]
C37  1uF  [CAP_0805J_AVX]
C38  10uF/50V  [CC1206]
C39  1uF/25V  [CC1206]
C40  10uF  [CC1206]
C41  100nF  [CAP_0805J_AVX]
C88  100nF  [CAP_0805J_AVX]
C89  10uF  [CC1206]
C91  10uF  [CC1206]
C92  10uF  [CC1206]
C93  10pF  [CAP_0805J_AVX]
C94  NM  [CAP_0805J_AVX]
L3  47uH  [WE-PD_1260]
L4  33uH  [WE-PD_1260]
Q7  2STR1160  [SOT23_3]
R24  150k  [SMD 0805]
R27  8.2k  [SMD 0805]
R31  402k  [SMD 0805]
R32  10k  [SMD 0805]
R33  82k  [SMD 0805]
R118  10k  [SMD 0805]
R119  1k  [SMD 0805]
R120  10k  [SMD 0805]
TP2  24V  [TP_20-313142]
TP3  GND  [TP_20-313142]
TP9  +16V  [Terminal]
TP10  +5V  [Terminal]
U6  L6981NDR  [SOIC-8]
U7  L6981NDR  [SOIC-8]

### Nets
+5V: C40.2 C41.2 C89.2 C91.2 C92.2 C93.2 L4.1 R31.2 TP10.1(AmpIn)
+16V: C35.2 C88.2 L3.1 R24.2 TP9.1(AmpIn)
+24V: C32.2 C33.2 C37.2 C38.2 R32.1 R118.2 TP2.1(AmpIn) U6.7(VIN) U7.7(VIN)
Gnd: C32.1 C33.1 C34.1 C35.1 C37.1 C38.1 C39.1 C40.1 C41.1 C88.1 C89.1 C91.1 C92.1 C94.1 Q7.2(E) R27.1 R33.1 R120.1 TP3.1(AmpIn) U6.6(AGND) U6.8(PGND) U7.6(AGND) U7.8(PGND)
16V_Enable: R119.2
NetC29_1: C29.1 U6.2(BOOT)
NetC29_2: C29.2 L3.2 U6.1(SW)
NetC34_2: C34.2 U6.3(VCC)
NetC36_1: C36.1 U7.2(BOOT)
NetC36_2: C36.2 L4.2 U7.1(SW)
NetC39_2: C39.2 U7.3(VCC)
NetC93_1: C93.1 R31.1 R33.2 U7.4(FB/VOUT)
NetC94_2: C94.2 R24.1 R27.2 U6.4(FB/VOUT)
NetQ7_1: Q7.1(B) R119.1 R120.2
NetQ7_3: Q7.3(C) R118.1 U6.5(EN/CLKIN(*))
NetR32_2: R32.2 U7.5(EN/CLKIN(*))

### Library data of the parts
C29 C32 C36 C37 C41 C88 C93 C94 = 08051A561JAT2A: No Description Available; Built_By: EMA_UL_Team; Vendor: AVX Corporation; SourceLibrary: AVX_2016-12-14_2; Type: DEV
C33-C35 C38-C40 C89 C91 C92 = 12061C104KAT2A: No Description Available; Vendor: AVX Corporation; Built_By: EMA_UL_Team; SourceLibrary: AVX_2012-08-08; Type: DEV
L3 = 744771147: Fixed Ind 47UH 2.21A 75 Mohm SMD; Manufacturer 1: Wurth Electronics
L4 = MSS1048T-224KL: General Purpose Inductor, 33uH, 20%, 1 Element, Ferrite-Core, SMD, 4747; Manufacturer 1: Wurth Electronics; Manufacturer Part Number 1: 744771133
Q7 = NPN 2STR1160: as Q2 on sheet STEVAL-KITXCBP_Power-Stage
R24 R27 R31-R33 R118-R120 = RESISTOR: RESISTOR 0805; SMT/THT: SMT
TP2 TP3 TP9 TP10 = TESTP: Test Point; SMT/THT: THT
U6 U7 = Voltage Regulator L6981: DC-DC Switching Synchronous Adjustable Buck Converter; Manufacturer 1: STMicroelectronics; Manufacturer Part Number 1: L6981CDR

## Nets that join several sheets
+5V: STEVAL-KITXCBP_Power-Stage (P7.6), STEVAL-KITXCBP_Voltage-Regulator (9 pins)
+16V: STEVAL-KITXCBP_Power-Stage (P7.4 R81.1 R82.2 R98.2), STEVAL-KITXCBP_Voltage-Regulator (5 pins)
+24V: STEVAL-KITXCBP_Power-Stage (12 pins), STEVAL-KITXCBP_Voltage-Regulator (9 pins)
Gnd: STEVAL-KITXCBP_Power-Stage (68 pins), STEVAL-KITXCBP_Voltage-Regulator (23 pins)
PE03: STEVAL-KITXCBP_Input-Mains-Filter (C46.2 C47.2 J4.2), STEVAL-KITXCBP_Power-Stage (7 pins)
16V_Enable: STEVAL-KITXCBP_Power-Stage (P7.16), STEVAL-KITXCBP_Voltage-Regulator (R119.2)
~Line: STEVAL-KITXCBP_Input-Mains-Filter (C45.2 L5.2 VR2.1), STEVAL-KITXCBP_Power-Stage (J18.1 K1.24 P12.2 R38.2)
~Line_pf: STEVAL-KITXCBP_Input-Mains-Filter (C42.1 CM2.3 L5.1), STEVAL-KITXCBP_Power-Stage (R7.1)
~Neutral: STEVAL-KITXCBP_Input-Mains-Filter (C42.2 C45.1 CM2.4 VR2.2), STEVAL-KITXCBP_Power-Stage (J18.2 K1.14 P12.1 R39.1)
